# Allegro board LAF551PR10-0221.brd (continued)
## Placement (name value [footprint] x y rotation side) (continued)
CG268  22U_0603_6.3V6M  [C_0603]  263.22 57.01 270 bottom
CG269  10U_0603_6.3V6M  [C_0603]  271.41 114.67 180 top
CG270  10U_0603_6.3V6M  [C_0603]  234.9 89.84 90 top
CG271  10U_0603_6.3V6M  [C_0603]  247.21 52.06 0 bottom
CG272  1U_0402_6.3V4Z  [C_0402]  235.53 81.13 90 top
CG273  1U_0402_6.3V4Z  [C_0402]  245.17 52.12 0 bottom
CG274  1U_0402_6.3V4Z  [C_0402]  192.97 70.16 0 bottom
CG275  1U_0402_6.3V4Z  [C_0402]  223.29 79.49 180 top
CG276  1U_0402_6.3V4Z  [C_0402]  190.57 79 270 bottom
CG277  1U_0402_6.3V4Z  [C_0402]  193.32 85.14 180 bottom
CG278  22U_0603_6.3V6M  [C_0603]  231.78 56.19 270 bottom
CG279  22U_0603_6.3V6M  [C_0603]  263.22 67.3 90 bottom
CG280  22U_0603_6.3V6M  [C_0603]  263.22 66.28 270 bottom
CG281  10U_0603_6.3V6M  [C_0603]  285.19 80.19 270 bottom
CG282  10U_0603_6.3V6M  [C_0603]  254.33 52 180 bottom
CG283  10U_0603_6.3V6M  [C_0603]  204.22 88.07 0 bottom
CG284  1U_0402_6.3V4Z  [C_0402]  193.67 104.19 0 bottom
CG285  1U_0402_6.3V4Z  [C_0402]  196.36 70.16 180 bottom
CG286  1U_0402_6.3V4Z  [C_0402]  224.24 52.12 180 bottom
CG287  1U_0402_6.3V4Z  [C_0402]  196.36 104.19 180 bottom
CG288  22U_0603_6.3V6M  [C_0603]  194.19 114.86 180 bottom
CG289  10U_0603_6.3V6M  [C_0603]  192.62 111.34 270 bottom
CG290  10U_0603_6.3V6M  [C_0603]  230.26 118.48 90 top
CG291  4.7U_0402_6.3V6M  [C_0402]  227.21 110.62 270 top
CG292  1U_0402_6.3V4Z  [C_0402]  192.78 112.93 90 bottom
CG293  0.1U_0201_6.3V6K  [C_0201]  194.18 110.57 270 bottom
CG294  0.1U_0201_6.3V6K  [C_0201]  192.3 112.25 180 bottom
CG295  4.7U_0402_6.3V6M  [C_0402]  220.54 103.99 90 top
CG296  4.7U_0402_6.3V6M  [C_0402]  218.06 107.43 0 top
CG297  4.7U_0402_6.3V6M  [C_0402]  236.8 110.37 270 top
CG298  1U_0402_6.3V4Z  [C_0402]  219.59 103.99 90 top
CG299  1U_0402_6.3V4Z  [C_0402]  221.32 108.7 180 top
CG300  1U_0402_6.3V4Z  [C_0402]  237.88 110.37 270 top
CG301  0.1U_0201_6.3V6K  [C_0201]  239.02 112.35 90 top
CG302  0.1U_0201_6.3V6K  [C_0201]  220.48 106.51 90 top
CG303  0.1U_0201_6.3V6K  [C_0201]  221.59 110.16 0 top
CG304  0.1U_0201_6.3V6K  [C_0201]  239.72 110.2 270 top
CG305  0.1U_0201_6.3V6K  [C_0201]  223.24 106.61 0 top
CG306  0.1U_0201_6.3V6K  [C_0201]  219.85 106.51 90 top
CG307  0.1U_0201_6.3V6K  [C_0201]  220.48 110.95 90 top
CG308  0.1U_0402_10V7K  [C_0402]  241.87 115.05 90 top
CG309  0.1U_0402_10V7K  [C_0402]  242.96 115.19 0 top
CG310  1U_0402_6.3V6K  [C_0402]  230.3 109.73 180 top
CG311  4.7U_0603_6.3V6M  [C_0603]  245.14 113.76 90 top
CG312  0.1U_0402_10V7K  [C_0402]  218.7 104 90 top
CG313  0.01U_0402_16V7K  [C_0402]  276.32 103.2 270 top
CG314  0.01U_0402_16V7K  [C_0402]  272.74 104.36 90 top
CG315  0.01U_0402_16V7K  [C_0402]  264.85 62.11 270 bottom
CG316  0.01U_0402_16V7K  [C_0402]  274.6 68.47 180 top
CG317  0.01U_0402_16V7K  [C_0402]  229.4 64.75 180 top
CG318  0.01U_0402_16V7K  [C_0402]  230.93 62.09 0 top
CG320  10U_0402_6.3V6M  [C_0402]  195.03 110.87 270 bottom
CG322  1U_0402_6.3V6K  [C_0402]  196.58 105.83 90 bottom
CG323  0.1U_0402_16V7K  [C_0402]  196.57 108.55 270 bottom
CG324  22U_0402_6.3V6M  [C_0402]  277.73 115.64 270 top
CG325  10U_0402_6.3V4Z  [C_0402]  271.36 111.5 180 top
CG326  10U_0402_6.3V4Z  [C_0402]  270.95 106.06 180 top
CG327  10U_0402_6.3V4Z  [C_0402]  279.32 112.25 180 top
CG328  1U_0402_6.3V4Z  [C_0402]  270.52 119.51 0 top
CG329  1U_0402_6.3V4Z  [C_0402]  273.8 114.8 0 top
CG330  1U_0402_6.3V4Z  [C_0402]  281.1 112.28 180 top
CG331  1U_0402_6.3V4Z  [C_0402]  273.8 113.86 0 top
CG332  1U_0402_6.3V4Z  [C_0402]  271.36 112.44 180 top
CG333  1U_0402_6.3V4Z  [C_0402]  278.33 106.12 0 top
CG334  1U_0402_6.3V4Z  [C_0402]  281.64 101.96 180 top
CG335  1U_0402_6.3V4Z  [C_0402]  273.03 95.77 0 top
CG336  1U_0402_6.3V4Z  [C_0402]  278.46 101.73 180 top
CG337  1U_0402_6.3V4Z  [C_0402]  272.27 87.79 0 top
CG338  1U_0402_6.3V4Z  [C_0402]  278.46 100.84 180 top
CG339  1U_0402_6.3V4Z  [C_0402]  278.98 94.92 180 top
CG340  1U_0402_6.3V4Z  [C_0402]  271.28 95.79 0 top
CG341  1U_0402_6.3V4Z  [C_0402]  269.54 95.79 0 top
CG342  1U_0402_6.3V4Z  [C_0402]  272.23 100.55 180 top
CG343  1U_0402_6.3V4Z  [C_0402]  270.46 100.54 180 top
CG344  22U_0402_6.3V6M  [C_0402]  262.48 55.5 270 top
CG345  10U_0402_6.3V4Z  [C_0402]  248.71 58.87 270 top
CG346  10U_0402_6.3V4Z  [C_0402]  248.69 56.2 90 top
CG347  10U_0402_6.3V4Z  [C_0402]  256.55 55.54 270 top
CG348  1U_0402_6.3V4Z  [C_0402]  259.67 52.38 180 top
CG349  1U_0402_6.3V4Z  [C_0402]  254.64 55.45 270 top
CG350  1U_0402_6.3V4Z  [C_0402]  256.37 57.56 270 top
CG351  1U_0402_6.3V4Z  [C_0402]  254.63 58.12 90 top
CG352  1U_0402_6.3V4Z  [C_0402]  257.31 66.09 270 top
CG353  1U_0402_6.3V4Z  [C_0402]  253.88 63.49 270 top
CG354  1U_0402_6.3V4Z  [C_0402]  272.12 84.51 0 top
CG355  1U_0402_6.3V4Z  [C_0402]  270.66 84.52 180 top
CG356  1U_0402_6.3V4Z  [C_0402]  269.57 79.87 0 top
CG357  1U_0402_6.3V4Z  [C_0402]  271.4 79.9 0 top
CG358  1U_0402_6.3V4Z  [C_0402]  280.93 71.3 0 top
CG359  1U_0402_6.3V4Z  [C_0402]  271.48 77.46 180 top
CG360  1U_0402_6.3V4Z  [C_0402]  277.61 75.02 270 top
CG361  1U_0402_6.3V4Z  [C_0402]  272.56 71.72 180 top
CG362  1U_0402_6.3V4Z  [C_0402]  275.17 74.92 90 top
CG363  1U_0402_6.3V4Z  [C_0402]  273.22 76.57 180 top
CG364  22U_0402_6.3V6M  [C_0402]  219.07 52.34 180 top
CG365  10U_0402_6.3V4Z  [C_0402]  219.81 63.41 270 top
CG366  10U_0402_6.3V4Z  [C_0402]  215.64 52.26 0 top
CG367  10U_0402_6.3V4Z  [C_0402]  221.38 64.35 270 top
CG368  1U_0402_6.3V4Z  [C_0402]  229.28 66.56 270 bottom
CG369  1U_0402_6.3V4Z  [C_0402]  220.09 57.67 90 top
CG370  1U_0402_6.3V4Z  [C_0402]  215.64 53.17 0 top
CG371  1U_0402_6.3V4Z  [C_0402]  213.79 52.29 0 top
CG372  1U_0402_6.3V4Z  [C_0402]  213.79 53.2 0 top
CG373  1U_0402_6.3V4Z  [C_0402]  223.68 59.64 0 top
CG374  1U_0402_6.3V4Z  [C_0402]  231.82 60.3 90 top
CG375  1U_0402_6.3V4Z  [C_0402]  232.23 66.37 90 top
CG376  1U_0402_6.3V4Z  [C_0402]  232.43 59.05 270 top
CG377  1U_0402_6.3V4Z  [C_0402]  235.1 52.4 180 top
CG378  1U_0402_6.3V4Z  [C_0402]  238.71 64.38 270 top
CG379  1U_0402_6.3V4Z  [C_0402]  238.64 55.57 270 top
CG380  1U_0402_6.3V4Z  [C_0402]  238.72 58.06 270 top
CG381  1U_0402_6.3V4Z  [C_0402]  236.51 59.67 180 top
CG382  1U_0402_6.3V4Z  [C_0402]  231.94 57.18 90 bottom
CG383  1U_0402_6.3V4Z  [C_0402]  232 63.81 270 bottom
CG384  0.1U_0402_10V7K  [C_0402]  194.37 106.1 0 top
CG385  10U_0402_6.3V6M  [C_0402]  197.46 108.55 270 bottom
CG386  0.1U_0402_10V7K  [C_0402]  196.74 116.31 0 bottom
CG387  0.01U_0402_16V7K  [C_0402]  199.25 87.85 90 bottom
CG388  0.01U_0402_16V7K  [C_0402]  200.12 86.29 270 bottom
CG389  22U_0402_6.3V6M  [C_0402]  191.26 100.8 270 top
CG390  10U_0402_6.3V4Z  [C_0402]  205.23 86.1 0 bottom
CG391  10U_0402_6.3V4Z  [C_0402]  194.64 88.7 180 bottom
CG392  10U_0402_6.3V4Z  [C_0402]  205.23 87 0 bottom
CG393  1U_0402_6.3V4Z  [C_0402]  200.87 104.19 180 top
CG394  1U_0402_6.3V4Z  [C_0402]  195.88 97.49 0 top
CG395  1U_0402_6.3V4Z  [C_0402]  202.92 103.22 180 top
CG396  1U_0402_6.3V4Z  [C_0402]  193.93 97.56 180 top
CG397  1U_0402_6.3V4Z  [C_0402]  202.61 95.8 0 top
CG398  1U_0402_6.3V4Z  [C_0402]  204.48 95.95 0 top
CG399  1U_0402_6.3V4Z  [C_0402]  194.65 69.75 180 top
CG400  1U_0402_6.3V4Z  [C_0402]  190.62 80.79 0 top
CG401  1U_0402_6.3V4Z  [C_0402]  204.9 70.42 0 top
CG402  1U_0402_6.3V4Z  [C_0402]  196.92 76.91 180 top
CG403  1U_0402_6.3V4Z  [C_0402]  197.95 80.57 90 top
CG404  1U_0402_6.3V4Z  [C_0402]  206.75 75.49 180 top
CG405  1U_0402_6.3V4Z  [C_0402]  191.36 75.29 270 top
CG406  1U_0402_6.3V4Z  [C_0402]  201.74 70.53 0 top
CG407  1U_0402_6.3V4Z  [C_0402]  204.02 70.44 90 top
CG408  1U_0402_6.3V4Z  [C_0402]  198.05 70.23 90 top
CG410  22U_0402_6.3V6M  [C_0402]  267.88 91.94 270 top
CG411  22U_0402_6.3V6M  [C_0402]  268.75 91.96 270 top
CG412  22U_0402_6.3V6M  [C_0402]  273.63 93.34 0 top
CG413  10U_0402_6.3V4Z  [C_0402]  278.51 97.46 180 top
CG414  10U_0402_6.3V4Z  [C_0402]  278.45 102.62 180 top
CG415  10U_0402_6.3V4Z  [C_0402]  279.82 94.91 0 top
CG416  1U_0402_6.3V4Z  [C_0402]  270.46 101.44 180 top
CG417  1U_0402_6.3V4Z  [C_0402]  268.63 96.54 90 top
CG418  1U_0402_6.3V4Z  [C_0402]  272.26 86.87 0 top
CG419  1U_0402_6.3V4Z  [C_0402]  271.78 93.75 180 top
CG420  1U_0402_6.3V4Z  [C_0402]  268.54 99.79 270 top
CG421  1U_0402_6.3V4Z  [C_0402]  276.7 96.59 0 top
CG422  1U_0402_6.3V4Z  [C_0402]  273.06 94.89 180 top
CG423  1U_0402_6.3V4Z  [C_0402]  275.64 91.84 90 top
CG424  1U_0402_6.3V4Z  [C_0402]  276.56 91.84 90 top
CG425  1U_0402_6.3V4Z  [C_0402]  269.55 94.81 0 top
CG426  22U_0402_6.3V6M  [C_0402]  259.69 51.49 180 top
CG427  22U_0402_6.3V6M  [C_0402]  263.36 55.52 270 top
CG428  22U_0402_6.3V6M  [C_0402]  255.51 58.12 90 top
CG429  10U_0402_6.3V4Z  [C_0402]  250.62 56.35 270 top
CG430  10U_0402_6.3V4Z  [C_0402]  254.05 52.47 180 top
CG431  10U_0402_6.3V4Z  [C_0402]  256.31 67.06 0 top
CG432  1U_0402_6.3V4Z  [C_0402]  254.69 65.83 90 top
CG433  1U_0402_6.3V4Z  [C_0402]  249.34 65.05 270 top
CG434  1U_0402_6.3V4Z  [C_0402]  263.34 57.31 270 top
CG435  1U_0402_6.3V4Z  [C_0402]  254.77 63.49 270 top
CG436  1U_0402_6.3V4Z  [C_0402]  257.21 52.43 180 top
CG437  1U_0402_6.3V4Z  [C_0402]  257.23 51.54 180 top
CG438  1U_0402_6.3V4Z  [C_0402]  258.83 62 180 top
CG439  1U_0402_6.3V4Z  [C_0402]  258.73 59.64 0 top
CG440  1U_0402_6.3V4Z  [C_0402]  254.06 51.58 180 top
CG441  1U_0402_6.3V4Z  [C_0402]  248.45 65.07 270 top
CG442  22U_0402_6.3V6M  [C_0402]  228.38 55.46 270 top
CG443  22U_0402_6.3V6M  [C_0402]  221.42 57.52 90 top
CG444  22U_0402_6.3V6M  [C_0402]  229.28 55.46 270 top
CG445  10U_0402_6.3V4Z  [C_0402]  227.48 57.25 270 top
CG446  10U_0402_6.3V4Z  [C_0402]  228.37 57.23 270 top
CG447  10U_0402_6.3V4Z  [C_0402]  227.5 55.46 270 top
CG448  1U_0402_6.3V4Z  [C_0402]  224.23 52.39 180 top
CG449  1U_0402_6.3V4Z  [C_0402]  222.3 59.31 180 top
CG450  1U_0402_6.3V4Z  [C_0402]  221.32 51.44 0 top
CG451  1U_0402_6.3V4Z  [C_0402]  221.32 52.34 0 top
CG452  1U_0402_6.3V4Z  [C_0402]  220.54 55.79 90 top
CG453  1U_0402_6.3V4Z  [C_0402]  220.35 53.7 180 top
CG454  1U_0402_6.3V4Z  [C_0402]  224.24 51.49 180 top
CG455  1U_0402_6.3V4Z  [C_0402]  221 65.83 90 top
CG456  1U_0402_6.3V4Z  [C_0402]  228.14 59.79 180 top
CG457  1U_0402_6.3V4Z  [C_0402]  221.42 55.78 90 top
CG458  22U_0402_6.3V6M  [C_0402]  201.7 95.86 270 top
CG459  22U_0402_6.3V6M  [C_0402]  197.18 103.81 270 top
CG460  22U_0402_6.3V6M  [C_0402]  192.02 103.58 0 top
CG461  10U_0402_6.3V4Z  [C_0402]  193.96 96.61 180 top
CG462  10U_0402_6.3V4Z  [C_0402]  204.26 97.25 0 top
CG463  10U_0402_6.3V4Z  [C_0402]  201.95 97.48 180 top
CG464  1U_0402_6.3V4Z  [C_0402]  200.14 98.42 270 top
CG465  1U_0402_6.3V4Z  [C_0402]  201.76 104.21 90 top
CG466  1U_0402_6.3V4Z  [C_0402]  202.8 104.11 90 top
CG467  1U_0402_6.3V4Z  [C_0402]  204.85 104.44 180 top
CG468  1U_0402_6.3V4Z  [C_0402]  190.33 92.9 270 top
CG469  1U_0402_6.3V4Z  [C_0402]  192.16 95.69 90 top
CG470  1U_0402_6.3V4Z  [C_0402]  191.3 98.11 90 top
CG471  1U_0402_6.3V4Z  [C_0402]  200.87 105.08 180 top
CG472  1U_0402_6.3V4Z  [C_0402]  198.61 94.44 0 top
CG473  1U_0402_6.3V4Z  [C_0402]  198.54 96.73 180 top
CG474  0.1U_0402_16V4Z  [C_0402]  197.89 113.25 0 top
CG475  0.1U_0402_16V4Z  [C_0402]  196.58 106.28 270 top
CG476  0.1U_0201_6.3V6K  [C_0201]  314.31 62.12 270 top
CG478  0.1U_0201_6.3V6K  [C_0201]  277.36 156.96 90 top
CG479  0.1U_0201_6.3V6K  [C_0201]  280.35 163.13 0 top
CG480  0.1U_0201_6.3V6K  [C_0201]  275.69 149.57 270 top
CG481  2200P_0402_25V7K  [C_0402]  281.64 164.34 180 top
CG482  0.047U_0402_16V4Z  [C_0402]  278.2 164.25 270 top
CG483  0.1U_0201_6.3V6K  [C_0201]  281.21 145.91 270 top
CG487  0.1U_0402_16V7K  [C_0402]  193.16 111.34 180 top
CG488  0.1U_0402_10V7K  [C_0402]  191.4 58.78 90 bottom
CG489  0.01U_0402_16V  [C_0402]  215.32 157.17 0 top
CH36  4.7U_0402_6.3V6M  [C_0402]  219.52 38.92 0 bottom
CH45  10P_0402_50V8J  [C_0402]  212.43 14.41 180 bottom
CH46  10P_0402_50V8J  [C_0402]  213.29 14.41 0 bottom
CH47  15P_0402_50V  [C_0402]  192.69 45.32 180 bottom
CH48  15P_0402_50V  [C_0402]  195.23 45.32 0 bottom
CH49  0.1U_0402_16V7K  [C_0402]  229.09 16.08 0 bottom
CH52  1U_0603_10V6K~D  [C_0603]  228.65 14.38 0 bottom
CH53  1U_0603_10V6K~D  [C_0603]  216.89 14.23 180 bottom
CH80  1U_0402_6.3V6K~D  [C_0402]  213.66 15.99 180 top
CH82  1U_0402_6.3V6K~D  [C_0402]  190.56 41.99 180 bottom
CH100  0.022U_0402_25V7K  [C_0402]  152.66 39.38 0 top
CH101  0.022U_0402_25V7K  [C_0402]  155.34 55.37 90 top
CH102  10U_0603_6.3V6M~D  [C_0603]  168.05 106.97 270 top
CH103  10U_0603_6.3V6M~D  [C_0603]  168.05 109.38 270 top
CH104  10U_0603_6.3V6M~D  [C_0603]  167.94 111.78 90 top
CH105  1U_0201_6.3V6M  [C_0201]  172.5 116.34 0 top
CH106  1U_0201_6.3V6M  [C_0201]  169.43 116.73 90 top
CH107  1U_0201_6.3V6M  [C_0201]  167.98 115.01 0 top
CH118  10U_0402_6.3V6M  [C_0402]  144.22 101.39 90 top
CH119  10U_0402_6.3V6M  [C_0402]  150.82 101.83 90 top
CH120  10U_0402_6.3V6M  [C_0402]  171.46 100.89 0 top
CH121  10U_0402_6.3V6M  [C_0402]  147.76 81.31 0 top
CH122  10U_0402_6.3V6M  [C_0402]  152.49 101.64 90 top
CH123  10U_0402_6.3V6M  [C_0402]  147.76 80.04 0 top
CH124  10U_0402_6.3V6M  [C_0402]  143.26 98.78 90 top
CH125  10U_0402_6.3V6M  [C_0402]  156.18 101.46 90 top
CH126  10U_0402_6.3V6M  [C_0402]  167.9 97.88 90 top
CH127  10U_0402_6.3V6M  [C_0402]  165.3 99.34 90 top
CH128  10U_0402_6.3V6M  [C_0402]  147.76 78.77 0 top
CH129  22U_0603_6.3V6M  [C_0603]  168.15 81.05 0 top
CH130  22U_0603_6.3V6M  [C_0603]  168.15 79.34 0 top
CH131  22U_0603_6.3V6M  [C_0603]  153.57 79.14 180 top
CH132  22U_0603_6.3V6M  [C_0603]  153.57 80.98 180 top
CH173  0.1U_0402_10V7K  [C_0402]  213.66 15.1 180 top
CH174  0.1U_0402_10V  [C_0402]  215.96 20.69 0 top
CH175  0.1U_0402_10V  [C_0402]  212.91 44.85 90 bottom
CH176  1U_0402_6.3V6K~D  [C_0402]  213.93 35.49 0 top
CH180  1U_0402_6.3V6K~D  [C_0402]  204.4 26.04 180 top
CH181  22U_0805_6.3V6M~D  [C_0805]  202.89 15.26 270 bottom
CH182  1U_0603_10V6K  [C_0603]  214.25 38.18 0 top
CH186  0.1U_0402_10V7K  [C_0402]  216.09 17.1 180 top
CH187  1U_0402_6.3V6K~D  [C_0402]  194.73 17.07 180 top
CH188  1U_0402_6.3V6K~D  [C_0402]  206.94 26.34 90 top
CH190  0.1U_0402_10V7K  [C_0402]  202.94 21.83 0 top
CH192  0.1U_0402_10V7K  [C_0402]  206.05 25.17 90 top
CH193  0.1U_0402_16V7K~D  [C_0402]  172.79 102.28 90 top
CH194  0.1U_0402_16V7K~D  [C_0402]  130.9 116.77 180 top
CH195  0.1U_0402_16V7K~D  [C_0402]  132.33 117.28 0 top
CH197  0.1U_0402_10V7K  [C_0402]  125.57 77.69 270 top
CH201  0.1U_0201_6.3V6K  [C_0201]  220.99 38.57 270 top
CH202  0.22U_0201_6.3V  [C_0201]  250.58 12.22 270 top
CH203  0.22U_0201_6.3V  [C_0201]  250.01 12.22 270 top
CH204  0.22U_0201_6.3V  [C_0201]  189.26 26.09 0 bottom
CH205  0.22U_0201_6.3V  [C_0201]  189.26 26.66 0 bottom
CH206  0.22U_0201_6.3V  [C_0201]  191.63 23.99 180 bottom
CH207  0.22U_0201_6.3V  [C_0201]  191.63 24.57 180 bottom
CH208  0.22U_0201_6.3V  [C_0201]  241.05 11.7 90 top
CH209  0.22U_0201_6.3V  [C_0201]  241.63 11.7 90 top
CH210  0.22U_0201_6.3V  [C_0201]  189.96 19.99 0 bottom
CH211  0.22U_0201_6.3V  [C_0201]  189.96 19.42 0 bottom
CH212  0.22U_0201_6.3V  [C_0201]  188.88 21.2 0 bottom
CH213  0.22U_0201_6.3V  [C_0201]  188.88 21.77 0 bottom
CH214  0.22U_0201_6.3V  [C_0201]  190.67 18.28 180 bottom
CH215  0.22U_0201_6.3V  [C_0201]  190.67 18.85 180 bottom
CH216  0.22U_0201_6.3V  [C_0201]  190.55 17.64 180 bottom
CH217  0.22U_0201_6.3V  [C_0201]  190.55 16.88 180 bottom
CH218  0.22U_0201_6.3V  [C_0201]  267.95 16.93 90 bottom
CH219  0.22U_0201_6.3V  [C_0201]  267.32 16.93 90 bottom
CH220  0.22U_0201_6.3V  [C_0201]  269.67 17.52 180 bottom
CH221  0.22U_0201_6.3V  [C_0201]  269.67 16.95 180 bottom
CH222  0.22U_0201_6.3V  [C_0201]  197.62 14.88 90 bottom
CH223  0.22U_0201_6.3V  [C_0201]  197.05 14.88 90 bottom
CH224  0.22U_0201_6.3V  [C_0201]  198.19 14.88 90 bottom
CH225  0.22U_0201_6.3V  [C_0201]  198.76 14.88 90 bottom
CH226  0.1U_0402_10V7K  [C_0402]  216.82 14.51 0 top
CH227  0.01U_0201_16V7  [C_0201]  188.29 24.48 270 bottom
CH228  0.01U_0201_16V7  [C_0201]  187.59 24.48 270 bottom
CH229  0.01U_0201_16V7  [C_0201]  104.66 13.03 90 bottom
CH230  0.01U_0201_16V7  [C_0201]  105.23 13.03 90 bottom
CH231  10P_0402_50V8J  [C_0402]  206.94 24.59 90 top
CH232  33P_0402_50V8J  [C_0402]  222.49 21.11 90 bottom
CH233  4.7U_0603_6.3V6M  [C_0603]  212.35 35.11 270 top
CI38  0.1U_0402_10V6K  [C_0402]  165.68 175.57 90 bottom
CI39  0.1U_0402_10V6K  [C_0402]  166.57 175.57 90 bottom
CL1  0.1U_0402_16V7K  [C_0402]  268.56 165.47 180 bottom
CL2  0.1U_0402_16V7K  [C_0402]  268.56 164.58 180 bottom
CL3  0.1U_0402_16V7K  [C_0402]  271.8 167.68 90 bottom
CL4  0.1U_0402_16V7K  [C_0402]  272.69 167.68 90 bottom
CL5  1U_0402_6.3V6K~D  [C_0402]  275.35 162.26 180 top
CL6  0.1U_0402_16V7K~D  [C_0402]  275.34 161.37 180 top
CL7  0.1U_0402_16V7K~D  [C_0402]  267.38 161.46 180 bottom
CL8  18P_0201_25V  [C_0201]  280.32 165.22 0 bottom
CL9  18P_0201_25V  [C_0201]  279.7 165.22 180 bottom
CL11  1000P_0402_50V7K~D  [C_0402]  276.63 166.93 0 bottom
CL12  0.1U_0402_16V7K~D  [C_0402]  269.59 168.82 180 top
CL13  1U_0402_6.3V6K~D  [C_0402]  269.59 167.94 180 top
CL14  10U_0603_6.3V6M~D  [C_0603]  269.77 169.9 180 top
CL15  10U_0603_6.3V6M~D  [C_0603]  269.77 171.17 180 top
CL16  0.1U_0402_16V7K~D  [C_0402]  272.54 159.59 90 top
CL17  1U_0402_6.3V6K~D  [C_0402]  274.3 159.59 90 top
CL18  1U_0402_6.3V6K~D  [C_0402]  275.35 163.15 180 top
CL19  0.1U_0402_16V7K~D  [C_0402]  275.34 164.04 180 top
CL20  0.1U_0402_16V7K~D  [C_0402]  271.6 166.4 270 top
CL21  1U_0402_6.3V6K~D  [C_0402]  270.71 166.4 270 top
CL22  4.7U_0603_6.3V6K~D  [C_0603]  272.51 167.31 90 top
CL23  0.1U_0402_16V7K~D  [C_0402]  269.82 166.4 270 top
CL24  0.1U_0402_16V7K~D  [C_0402]  273.43 159.59 90 top
CL25  0.1U_0402_16V7K~D  [C_0402]  271.65 159.59 90 top
CL27  470P_0402_50V7K  [C_0402]  242.71 171.83 270 top
CL28  470P_0402_50V7K  [C_0402]  263.47 160.21 270 top
CL29  470P_0402_50V7K  [C_0402]  264.36 160.21 270 top
CL30  10P_1808_3KV7K~D  [C_1808]  263.03 160.46 90 bottom
CL31  470P_0402_50V7K  [C_0402]  266.12 161.6 0 top
CL32  1000P_0402_50V7K~D  [C_0402]  250.83 158.56 270 top
CL33  0.1U_0402_16V7K~D  [C_0402]  247.91 157.65 90 top
CL34  1000P_0402_50V7K~D  [C_0402]  247.02 158.56 270 top
CL35  0.1U_0402_16V7K~D  [C_0402]  249.94 157.65 90 top
CL36  1000P_0402_50V7K~D  [C_0402]  254.96 158.56 270 top
CL37  0.1U_0402_16V7K~D  [C_0402]  255.85 157.65 90 top
CL38  1000P_0402_50V7K~D  [C_0402]  257.44 158.56 270 top
CL39  0.1U_0402_16V7K~D  [C_0402]  258.33 157.65 90 top
CL40  4.7U_0805_10V4Z  [C_0805]  269.97 173.47 180 bottom
CL41  0.1U_0402_16V7K  [C_0402]  271.03 173.02 90 bottom
CL42  0.1U_0402_16V7K  [C_0402]  266.96 172.09 270 bottom
CL43  1U_0402_6.3V6K~D  [C_0402]  273.38 166.4 270 top
CL44  0.1U_0402_16V7K~D  [C_0402]  272.49 166.4 270 top
CLRP1  SHORT PADS  [SHORTPADS]  173.94 35.87 90 bottom
CM9  0.1U_0402_10V7K  [C_0402]  134.11 162.19 90 bottom
CM10  0.1U_0402_10V7K  [C_0402]  302.88 43.79 90 top
CM11  4.7U_0805_10V4Z  [C_0805]  314.23 43.87 180 top
CM12  22U_0603_6.3V6M~D  [C_0603]  301.8 42.59 90 top
CM13  0.1U_0402_10V7K~D  [C_0402]  300.72 42.58 90 top
CM14  22U_0603_6.3V6M~D  [C_0603]  315.54 43.17 90 top
CM15  0.1U_0402_10V7K~D  [C_0402]  315.73 41.98 270 top
CM16  0.1U_0402_10V7K  [C_0402]  172.4 161.22 0 bottom
CM17  0.1U_0402_10V7K  [C_0402]  172.4 162.11 0 bottom
CM18  0.1U_0402_10V7K  [C_0402]  168.41 163.17 90 bottom
CM19  22U_0603_6.3V6M  [C_0603]  165.91 154.13 180 bottom
CM20  0.1U_0402_10V7K  [C_0402]  168.34 154.16 270 bottom
CM21  1U_0402_6.3V  [C_0402]  165.11 162.82 90 top
CM23  0.1U_0402_10V7K  [C_0402]  162.25 176.29 270 bottom
CM29  10U_0603_6.3V6M  [C_0603]  125.98 153.19 0 top
CM30  1U_0402_6.3V  [C_0402]  125.23 157 180 bottom
CM31  10U_0603_6.3V6M  [C_0603]  125.98 154.97 0 top
CM32  0.1U_0402_10V7K  [C_0402]  131.12 153.27 270 bottom
CM33  1U_0402_6.3V  [C_0402]  125.23 157.89 180 bottom
CM34  0.1U_0402_10V7K  [C_0402]  138.43 157.34 0 bottom
CM35  0.1U_0402_10V7K  [C_0402]  129.6 153.27 270 bottom
CM36  0.1U_0402_10V7K  [C_0402]  130.74 162.19 90 bottom
CM62  0.22U_0201_6.3V  [C_0201]  133.22 150.45 90 bottom
CM63  0.22U_0201_6.3V  [C_0201]  132.97 152.35 90 bottom
CM64  0.22U_0201_6.3V  [C_0201]  136.9 150.45 90 bottom
CM65  0.22U_0201_6.3V  [C_0201]  136.01 150.45 90 bottom
CM66  0.22U_0201_6.3V  [C_0201]  132.08 152.35 90 bottom
CM67  0.22U_0201_6.3V  [C_0201]  135.57 152.35 90 bottom
CM68  0.22U_0201_6.3V  [C_0201]  134.11 150.45 90 bottom
CM69  0.22U_0201_6.3V  [C_0201]  134.68 152.35 90 bottom
CM70  0.1U_0402_10V7K  [C_0402]  149.61 172.72 270 bottom
CM98  0.01U_0402_16V7K  [C_0402]  163.36 164.61 180 bottom
CM99  0.01U_0402_16V7K  [C_0402]  163.36 163.48 180 bottom
CM100  10P_0402_50V8J  [C_0402]  318.58 42.95 90 top
CN9  1U_0402_10V6K  [C_0402]  312.81 41.08 90 top
CN23  0.1U_0402_16V7K  [C_0402]  314.32 39.49 180 top
CN24  0.1U_0402_16V7K  [C_0402]  314.32 38.46 180 top
CN25  1U_0402_10V6K  [C_0402]  316.67 38.76 0 top
CS1  10U_0603_25V6M  [C_0603]  127.45 11.93 270 top
CS2  10U_0603_6.3V6M  [C_0603]  183.99 64.25 180 top
CS5  1000P_0402_50V7K~D  [C_0402]  125.48 11.94 270 top
CS6  0.1U_0402_25V6K~D  [C_0402]  126.37 11.94 270 top
CS7  0.1U_0402_16V4Z  [C_0402]  182.58 68 180 top
CS16  22U_0402_6.3V6M  [C_0402]  125.68 13.25 90 top
CT1  0.22U_0201_6.3V  [C_0201]  188.35 164.41 180 top
CT2  0.22U_0201_6.3V  [C_0201]  188.35 164.98 180 top
CT3  0.22U_0201_6.3V  [C_0201]  188.35 162.12 180 top
CT4  0.22U_0201_6.3V  [C_0201]  188.35 166.12 180 top
CT5  0.22U_0201_6.3V  [C_0201]  188.35 168.41 180 top
CT6  0.1U_0201_6.3V6K  [C_0201]  177.42 159.23 90 top
CT7  0.1U_0201_6.3V6K  [C_0201]  177.99 159.23 90 top
CT8  0.1U_0201_6.3V6K  [C_0201]  179.14 159.23 90 top
CT9  0.1U_0201_6.3V6K  [C_0201]  178.57 159.23 90 top
CT10  0.1U_0201_6.3V6K  [C_0201]  180.28 159.23 90 top
CT11  0.1U_0201_6.3V6K  [C_0201]  181.42 159.23 90 top
CT12  0.22U_0201_6.3V  [C_0201]  188.35 165.55 180 top
CT13  0.22U_0201_6.3V  [C_0201]  188.35 163.84 180 top
CT14  0.22U_0201_6.3V  [C_0201]  190.71 162.71 180 top
CT15  0.22U_0201_6.3V  [C_0201]  188.35 161.55 180 top
CT16  0.22U_0201_6.3V  [C_0201]  190.71 162.14 180 top
CT18  0.22U_0201_6.3V  [C_0201]  188.35 166.7 180 top
CT21  0.22U_0201_6.3V  [C_0201]  188.35 168.98 180 top
CT23  0.1U_0201_6.3V6K  [C_0201]  179.71 159.23 90 top
CT24  0.1U_0201_6.3V6K  [C_0201]  180.85 159.23 90 top
CT25  0.1U_0201_6.3V6K  [C_0201]  179.39 154.49 90 bottom
CT26  0.1U_0201_6.3V6K  [C_0201]  178.82 154.49 90 bottom
CT27  0.1U_0201_6.3V6K  [C_0201]  182.57 159.23 90 top
CT28  0.1U_0201_6.3V6K  [C_0201]  182 159.23 90 top
CT29  0.1U_0201_6.3V6K  [C_0201]  183.71 159.23 90 top
CT30  0.1U_0201_6.3V6K  [C_0201]  183.14 159.23 90 top
CT31  0.1U_0201_6.3V6K  [C_0201]  184.85 159.23 90 top
CT32  0.1U_0201_6.3V6K  [C_0201]  184.28 159.23 90 top
CT33  0.1U_0201_6.3V6K  [C_0201]  186 159.23 90 top
CT34  0.1U_0201_6.3V6K  [C_0201]  185.42 159.23 90 top
CT35  0.1U_0201_6.3V6K  [C_0201]  181.35 154.49 90 bottom
CT36  0.1U_0201_6.3V6K  [C_0201]  181.95 154.48 90 bottom
CT37  27P_0201_25V  [C_0201]  189.44 167.55 90 bottom
CT38  27P_0201_25V  [C_0201]  189.44 166.92 270 bottom
CT39  0.22U_0201_6.3V  [C_0201]  183.15 174.48 270 top
CT40  0.22U_0201_6.3V  [C_0201]  182.58 174.48 270 top
CT41  0.22U_0201_6.3V  [C_0201]  184.04 174.48 270 top
CT42  0.22U_0201_6.3V  [C_0201]  184.61 174.48 270 top
CT43  0.1U_0201_6.3V6K  [C_0201]  182.62 161.47 90 bottom
CT44  0.1U_0201_6.3V6K  [C_0201]  182.05 161.47 90 bottom
CT45  0.1U_0201_6.3V6K  [C_0201]  188.9 153.9 180 bottom
CT46  0.1U_0201_6.3V6K  [C_0201]  178.75 164.34 270 bottom
CT47  1U_0201_6.3V6M  [C_0201]  178.11 169.48 270 bottom
CT48  1U_0201_6.3V6M  [C_0201]  176.17 172.8 180 bottom
CT49  1U_0201_6.3V6M  [C_0201]  176.43 173.92 180 top
CT50  10U_0402_6.3V6M  [C_0402]  176.87 174.68 180 top
CT51  10U_0402_6.3V6M  [C_0402]  176.87 175.57 180 top
CT52  10U_0402_6.3V6M  [C_0402]  176.87 176.46 180 top
CT53  10U_0402_6.3V6M  [C_0402]  177.73 176.46 0 top
CT54  1U_0201_6.3V6M  [C_0201]  180.03 166.84 270 bottom
CT55  1U_0201_6.3V6M  [C_0201]  184.57 165.6 0 bottom
CT56  1U_0201_6.3V6M  [C_0201]  187.18 159.85 180 top
CT57  1U_0201_6.3V6M  [C_0201]  175.45 154.82 270 bottom
CT58  1U_0201_6.3V6M  [C_0201]  174.81 154.82 270 bottom
CT59  1U_0201_6.3V6M  [C_0201]  181.29 167.01 270 bottom
CT60  1U_0201_6.3V6M  [C_0201]  181.86 164.33 270 bottom
CT61  1U_0201_6.3V6M  [C_0201]  179.38 166.82 270 bottom
CT62  1U_0201_6.3V6M  [C_0201]  178.6 167.48 180 bottom
CT63  1U_0201_6.3V6M  [C_0201]  179.4 170.4 270 bottom
CT64  1U_0201_6.3V6M  [C_0201]  180.41 171.02 90 bottom
CT65  1U_0201_6.3V6M  [C_0201]  179.84 171.02 90 bottom
CT66  1U_0201_6.3V6M  [C_0201]  180.98 171.02 90 bottom
CT67  1U_0201_6.3V6M  [C_0201]  179.24 171.61 180 bottom
CT68  1U_0201_6.3V6M  [C_0201]  179.24 171.03 180 bottom
CT69  1U_0201_6.3V6M  [C_0201]  181.56 171.02 90 bottom
CT70  1U_0201_6.3V6M  [C_0201]  187.8 159.79 0 top
CT71  1U_0201_6.3V6M  [C_0201]  183.93 166.23 0 bottom
CT72  1U_0201_6.3V6M  [C_0201]  183.12 166.23 180 bottom
CT73  47U_0603_6.3V6M  [C_0603]  173.44 175.02 90 bottom
CT74  47U_0603_6.3V6M  [C_0603]  172.22 175.02 90 bottom
CT75  47U_0603_6.3V6M  [C_0603]  171 175.02 90 bottom
CT77  1U_0201_6.3V6M  [C_0201]  183.17 164.37 0 bottom
CT78  1U_0201_6.3V6M  [C_0201]  179.38 164.34 270 bottom
CT79  1U_0201_6.3V6M  [C_0201]  181.29 165.22 90 bottom
CT80  1U_0201_6.3V6M  [C_0201]  180.03 165.05 90 bottom
CT81  10U_0402_6.3V6M  [C_0402]  183.54 170.6 90 bottom
CT82  10U_0402_6.3V6M  [C_0402]  182.65 170.6 90 bottom
CT83  1U_0201_6.3V6M  [C_0201]  181.15 168.96 180 bottom
CT84  1U_0201_6.3V6M  [C_0201]  183.42 168.77 0 bottom
CT85  1U_0201_6.3V6M  [C_0201]  183.97 168.05 270 bottom
CT86  1U_0201_6.3V6M  [C_0201]  182.63 168.13 90 bottom
CT88  0.1U_0402_10V6K  [C_0402]  195.6 166.36 180 top
CT90  22U_0603_6.3V6M  [C_0603]  203.83 160.11 180 bottom
CT91  22U_0603_6.3V6M  [C_0603]  203.83 158.85 180 bottom
CT92  22U_0603_6.3V6M  [C_0603]  204.72 161.95 0 bottom
CT93  22U_0603_6.3V6M  [C_0603]  204.72 163.16 0 bottom
CT94  0.47U_0402_25V6K  [C_0402]  194.9 181.35 180 top
CT95  0.47U_0402_25V6K  [C_0402]  190.31 179.75 0 top
CT96  0.47U_0402_25V6K  [C_0402]  193.18 179.42 0 top
CT97  0.47U_0402_25V6K  [C_0402]  191.28 181.39 180 top
CT98  2.2U_0603_16V6K  [C_0603]  195.75 163.02 180 bottom
CT99  4.7U_0603_10V6K  [C_0603]  196.8 160.35 180 bottom
CT100  4.7U_0603_10V6K  [C_0603]  198.26 166.93 90 top
CT101  1U_0402_6.3V6K  [C_0402]  197.1 165.98 0 top
CT102  1U_0201_6.3V6M  [C_0201]  196.24 169.32 90 top
CT103  10U_0402_6.3V6M  [C_0402]  196.12 165 270 bottom
CT104  0.22U_0402_10V4Z  [C_0402]  202.63 168.99 90 bottom
CT106  1U_0603_25V6K  [C_0603]  204.61 162.74 180 top
CT108  0.22U_0201_6.3V  [C_0201]  188.35 167.84 180 top
CT109  0.22U_0201_6.3V  [C_0201]  188.35 167.27 180 top
CT110  0.22U_0201_6.3V  [C_0201]  188.35 169.55 180 top
CT111  0.22U_0201_6.3V  [C_0201]  188.35 170.12 180 top
CT112  220P_0201_25V7K  [C_0201]  202.95 167.58 270 top
CT113  220P_0201_25V7K  [C_0201]  203.75 168.21 270 top
CT114  100P_0402_50V8J~D  [C_0402]  185.23 9.96 0 top
CT115  0.047U_0402_25V7K  [C_0402]  186.78 7.85 90 top
CT116  10U_0603_6.3V6M~D  [C_0603]  188.16 13.34 180 bottom
CT117  2200P_0402_25V7K  [C_0402]  192.24 9.52 180 top
CT118  0.1U_0402_10V6K  [C_0402]  193.86 7.8 0 top
CT153  1U_0201_6.3V6M  [C_0201]  181.9 165.54 0 bottom
CT154  47U_0603_6.3V6M  [C_0603]  175.94 168.05 180 bottom
CT155  47U_0603_6.3V6M  [C_0603]  175.94 169.24 180 bottom
CT156  22P_0402_50V8J~D  [C_0402]  195.36 158.68 0 bottom
CT157  22P_0402_50V8J~D  [C_0402]  197.25 159.01 45 bottom
CU2  47U_0805_6.3V6M  [C_0805]  20.11 45.43 0 bottom
CU3  10U_0603_6.3V6M~D  [C_0603]  20.58 40.76 0 bottom
CU6  150U_B2_6.3VM_R35M  [C_B2]  20.31 42.98 180 bottom
CU7  0.1U_0402_16V7K  [C_0402]  20.21 42.22 180 top
CU10  47U_0805_6.3V6M  [C_0805]  321.88 22.39 90 top
CU11  10U_0603_6.3V6M~D  [C_0603]  319.97 21.97 180 top
CU12  0.1U_0402_10V7K  [C_0402]  24.16 41.49 0 top
CU13  0.1U_0402_10V7K  [C_0402]  24.16 40.6 0 top
CU16  0.1U_0402_16V7K  [C_0402]  318.46 26.67 180 top
CU17  0.1U_0402_16V7K  [C_0402]  319.39 26.67 0 top
CU18  0.47U_0402_25V6K  [C_0402]  11.06 64.95 90 bottom
CU19  0.47U_0402_25V6K  [C_0402]  12.32 59.11 0 bottom
CU20  0.47U_0402_25V6K  [C_0402]  11.06 64.06 270 bottom
CU21  0.47U_0402_25V6K  [C_0402]  10.3 59.19 270 bottom
CU26  0.1U_0402_16V7K  [C_0402]  18.3 35.41 90 top
CU27  2.2U_0603_6.3V6K  [C_0603]  22.93 36.31 90 top
CU28  0.1U_0402_16V7K  [C_0402]  31.12 45.41 270 top
CU29  0.1U_0402_16V7K  [C_0402]  20.95 37.96 0 top
CU32  2.2U_0603_25V6K  [C_0603]  12.52 58.03 0 bottom
CU33  47U_0603_6.3V6M  [C_0603]  29.92 46.54 270 bottom
CU34  0.1U_0402_16V7K  [C_0402]  28.85 47.87 180 top
CU35  0.1U_0402_16V7K  [C_0402]  28.28 46.09 180 top
CU37  10U_0805_25V6K  [C_0805]  12.56 56.57 0 bottom
CU40  150U_B2_6.3VM_R35M  [C_B2]  12.2 54.26 90 bottom
CU42  47U_0603_6.3V6M  [C_0603]  29.41 48.95 180 top
CU44  47U_0603_6.3V6M  [C_0603]  30.01 49.27 90 bottom
CU45  0.1U_0402_10V7K  [C_0402]  321.71 21.38 0 top
CU46  0.1U_0402_10V7K  [C_0402]  315.3 25.29 90 top
CU47  0.1U_0402_10V7K  [C_0402]  21.46 46.79 0 bottom
CU48  10U_0402_6.3V6M  [C_0402]  316.2 25.3 90 top
CU49  0.22U_0402_10V6K  [C_0402]  16.96 48.45 270 top
CU50  0.22U_0402_10V6K  [C_0402]  17.85 48.45 270 top
CU51  15P_0402_50V  [C_0402]  11.03 54.77 270 top
CU52  15P_0402_50V  [C_0402]  12.35 53.78 270 top
CU53  0.1U_0603_50V7K  [C_0603]  24.06 52.75 225 top
CU54  10U_0603_6.3V6M  [C_0603]  24.89 51.86 225 top
CU55  0.1U_0603_50V7K  [C_0603]  23.06 56.12 90 top
CU56  22U_0402_6.3V6M  [C_0402]  21.14 57.59 0 top
CU65  0.1U_0402_16V7K  [C_0402]  22.87 52.11 0 bottom
CU66  10U_0603_6.3V6M  [C_0603]  16.65 56.32 270 bottom
CU68  1U_0805_25V6K  [C_0805]  19.25 50 90 bottom
CU70  1000P_0402_50V8-J  [C_0402]  15.93 53.14 0 bottom
CU72  1000P_0402_50V8-J  [C_0402]  20.58 50.4 90 bottom
CU76  0.1U_0402_16V7K  [C_0402]  31.21 49.33 180 top
CU77  0.1U_0402_10V7K  [C_0402]  34.31 52.89 180 top
CU78  1U_0402_6.3V6K  [C_0402]  35.89 50.61 270 top
CU79  0.22U_0402_10V6K  [C_0402]  13.97 64.76 0 top
CU80  0.22U_0402_10V6K  [C_0402]  13.97 63.87 0 top
CU81  0.22U_0402_10V6K  [C_0402]  13.59 58.03 0 top
CU82  0.22U_0402_10V6K  [C_0402]  13.59 58.92 0 top
CU83  0.22U_0402_10V6K  [C_0402]  19.63 48.45 270 top
CU84  0.22U_0402_10V6K  [C_0402]  18.74 48.45 270 top
CU85  0.1U_0603_50V7K  [C_0603]  21.03 48.5 0 top
CU86  0.01U_0402_16V7K  [C_0402]  22.37 49.97 180 bottom
CU87  1000P_0402_50V8-J  [C_0402]  17.87 49.8 90 bottom
CU88  1U_0402_6.3V  [C_0402]  14.92 51.43 0 bottom
CU89  1000P_0402_50V8-J  [C_0402]  21.46 52.19 180 bottom
CU90  22U_0402_6.3V6M  [C_0402]  23.32 53.53 225 top
CU91  0.1U_0402_16V7K  [C_0402]  36.78 50.61 270 top
CU92  0.1U_0402_16V7K  [C_0402]  32.52 52.87 90 top
CU93  4.7U_0402_6.3V6M  [C_0402]  16.98 49.99 90 bottom
CV1  0.1U_0201_6.3V6K  [C_0201]  147.07 169.07 270 top
CV2  0.1U_0201_6.3V6K  [C_0201]  147.71 169.07 270 top
CV3  0.1U_0201_6.3V6K  [C_0201]  148.41 169.38 270 top
CV4  0.1U_0201_6.3V6K  [C_0201]  149.04 169.38 270 top
CV5  10U_0603_6.3V6M  [C_0603]  162.25 167.15 90 bottom
CV6  0.1U_0201_6.3V6K  [C_0201]  150.24 169.38 270 top
CV7  0.1U_0201_6.3V6K  [C_0201]  150.47 168.04 270 top
CV8  0.1U_0201_6.3V6K  [C_0201]  149.6 169.38 270 top
CV9  47U_0603_6.3V6M  [C_0603]  163.97 169.98 0 bottom
CV10  10U_0603_6.3V6M  [C_0603]  162.89 171 180 bottom
CV11  0.1U_0201_6.3V6K  [C_0201]  151.1 168.04 270 top
CV12  0.1U_0201_6.3V6K  [C_0201]  151.34 169.38 270 top
CV13  0.1U_0201_6.3V6K  [C_0201]  151.98 169.38 270 top
CV14  0.1U_0603_25V7K  [C_0603]  173.1 184.2 0 top
CV15  1000P_0402_50V7K  [C_0402]  152.79 170.12 270 bottom
CV17  0.1U_0402_10V7K  [C_0402]  164.47 171.02 0 bottom
CV18  10U_0603_6.3V6M  [C_0603]  162.89 169.66 180 bottom
CV19  0.1U_0402_10V7K  [C_0402]  166.98 173.7 180 bottom
CV20  0.1U_0402_16V7K  [C_0402]  223.11 161.84 90 bottom
CV21  4.7U_0805_10V4Z  [C_0805]  166.72 171.69 270 bottom
CV23  0.1U_0201_6.3V6K  [C_0201]  243.66 161.69 90 top
CV24  0.1U_0201_6.3V6K  [C_0201]  226.42 162.23 270 bottom
CV25  0.1U_0201_6.3V6K  [C_0201]  225.85 162.23 270 bottom
CV26  0.1U_0201_6.3V6K  [C_0201]  230.28 168.48 90 bottom
CV27  0.1U_0201_6.3V6K  [C_0201]  229.33 168.48 90 bottom
CV28  0.1U_0201_6.3V6K  [C_0201]  241.48 169.31 90 top
CV29  0.1U_0201_6.3V6K  [C_0201]  234.7 169.37 90 bottom
CV30  0.1U_0201_6.3V6K  [C_0201]  242.37 169.31 90 top
CV31  0.1U_0201_6.3V6K  [C_0201]  235.45 169.37 90 bottom
CV32  0.1U_0201_6.3V6K  [C_0201]  241.65 168.48 90 bottom
CV33  0.1U_0201_6.3V6K  [C_0201]  240.76 168.48 90 bottom
CV34  10U_0402_6.3V6M  [C_0402]  238.73 168.84 180 bottom
CV35  0.1U_0201_6.3V6K  [C_0201]  238.68 169.6 180 bottom
CV36  0.1U_0402_10V7K  [C_0402]  164.55 165.5 0 top
CV37  10P_0402_50V8J  [C_0402]  166.89 166.6 0 bottom
CV372  10U_0603_6.3V6M  [C_0603]  162.38 165.73 180 bottom
CV373  10P_0402_50V8J  [C_0402]  164.46 171.92 0 bottom
CV374  10P_0402_50V8J  [C_0402]  164.35 164.58 0 top
CV375  10P_0402_50V8J  [C_0402]  170.16 184.25 180 top
CV1056  0.1U_0402_16V7K  [C_0402]  211.41 157.52 0 bottom
CV1057  0.1U_0201_6.3V6K  [C_0201]  218.3 166.02 270 bottom
CV1058  0.1U_0201_6.3V6K  [C_0201]  217.74 166.03 270 bottom
CV1059  0.1U_0201_6.3V6K  [C_0201]  212.91 166.07 270 bottom
CV1060  0.1U_0201_6.3V6K  [C_0201]  213.48 166.07 270 bottom
CV1061  0.1U_0201_6.3V6K  [C_0201]  215.34 166.04 270 bottom
CV1062  0.1U_0201_6.3V6K  [C_0201]  215.9 166.04 270 bottom
CV1063  0.1U_0201_6.3V6K  [C_0201]  210.52 166.08 270 bottom
CV1064  0.1U_0201_6.3V6K  [C_0201]  211.1 166.09 270 bottom
CV1068  10U_0603_6.3V6M~D  [C_0603]  222.26 171.12 0 bottom
CV1069  0.1U_0201_6.3V6K  [C_0201]  222.6 172.01 0 bottom
CX1  0.1U_0402_16V7K  [C_0402]  232.21 169.4 270 bottom
CX2  0.1U_0402_16V7K  [C_0402]  209.28 163.21 180 bottom
DA1  -  [BAT54C-7-F_SOT23-3]  38.35 27.23 270 top
DA2  BAT54AW_SOT323-3~D  [BAT54AW_SOT323-3]  36.86 24.37 90 bottom
DA3  BAT54AW_SOT323-3~D  [BAT54AW_SOT323-3]  35.14 43.2 180 top
DA4  AZ5125-02S.R7G_SOT23-3  [AZ5125-02SPR7G_SOT23-3]  22.45 19.99 270 bottom
DA5  AZ5123-02S SOT23  [AZ5125-02SPR7G_SOT23-3]  22.45 19.99 90 top
DA6  AZ5125-02S.R7G_SOT23-3  [AZ5125-02SPR7G_SOT23-3]  21.03 34.88 0 bottom
DA7  AZ5125-02S.R7G_SOT23-3  [AZ5125-02SPR7G_SOT23-3-NPM]  48.77 13.34 90 top
DA8  AZ5125-02S.R7G_SOT23-3  [AZ5125-02SPR7G_SOT23-3-NPM]  48.77 9.34 90 top
DE1  SDMK0340L-7-F_SOD323-2~D  [SDMK0340L-7-F_SOD323-2]  313.26 23.87 0 top
DE2  -  [RB751V-40_SOD323-2]  225.34 38.97 270 bottom
DE3  -  [RB751V-40_SOD323-2]  223.64 38.97 270 bottom
DE4  -  [RB751V-40_SOD323-2]  227.06 38.97 270 bottom
DF1  -  [SDMK0340L-7-F_SOD323-2]  102.93 61.58 270 top
DF2  -  [SDMK0340L-7-F_SOD323-2]  293.45 73.88 180 top
DG2  RB751S40T1G_SOD523-2  [RB520SM-30T2R_EMD2-2]  214.75 112.47 0 bottom
DG3  RB751S40T1G_SOD523-2  [RB520SM-30T2R_EMD2-2]  281.3 173.77 270 top
DG4  RB751S40T1G_SOD523-2  [RB520SM-30T2R_EMD2-2]  213.19 161.08 0 top
DG6  RB751S40T1G_SOD523-2  [RB520SM-30T2R_EMD2-2]  277.59 166.88 270 top
DG7  RB751S40T1G_SOD523-2  [RB520SM-30T2R_EMD2-2]  281.3 169.33 90 top
DG8  RB751S40T1G_SOD523-2  [RB520SM-30T2R_EMD2-2]  186.76 35.87 90 bottom
DG9  RB751S40T1G_SOD523-2  [RB520SM-30T2R_EMD2-2]  188.22 38.67 180 bottom
DH1  -  [RB751V-40_SOD323-2]  201.31 10.02 0 bottom
DK1  -  [TVNST52302AB0_SOT523-3]  144.79 3.6 180 top
DK2  -  [TVNST52302AB0_SOT523-3]  137.09 3.34 180 top
DK3  -  [TVNST52302AB0_SOT523-3]  141.7 4.96 270 top
DS1  SDM10U45-7_SOD523-2~D  [RB520SM-30T2R_EMD2-2]  188.13 66.54 270 top
DT1  SDM10U45-7_SOD523-2~D  [RB520SM-30T2R_EMD2-2]  190.78 177.09 90 top
DT2  AZ5B75-01B  [ESD108-B1-CSP0201_WLL-2-1-2]  190.12 177.64 180 bottom
DT3  AZ5B75-01B  [ESD108-B1-CSP0201_WLL-2-1-2]  190.78 177.64 0 bottom
DT4  AZ5B75-01B  [ESD108-B1-CSP0201_WLL-2-1-2]  187.21 176.33 180 bottom
DT5  AZ5B75-01B  [ESD108-B1-CSP0201_WLL-2-1-2]  187.91 176.33 0 bottom
DT6  AZ5B75-01B  [ESD108-B1-CSP0201_WLL-2-1-2]  196.27 175.92 0 top
DT7  AZ5B75-01B  [ESD108-B1-CSP0201_WLL-2-1-2]  195.61 175.92 180 top
DT8  AZ5B75-01B  [ESD108-B1-CSP0201_WLL-2-1-2]  196.31 175.92 0 bottom
DT9  AZ5B75-01B  [ESD108-B1-CSP0201_WLL-2-1-2]  195.61 175.92 180 bottom
DT10  -  [TVWDF1004AD0_DFN9]  191.81 176.17 0 bottom
DT11  AZ5B75-01B  [ESD108-B1-CSP0201_WLL-2-1-2]  191.27 175.57 0 top
DT12  AZ5B75-01B  [ESD108-B1-CSP0201_WLL-2-1-2]  196.9 177.67 90 top
DT13  AZ5B75-01B  [ESD108-B1-CSP0201_WLL-2-1-2]  194.8 177.66 90 top
DT14  AZ5B75-01B  [ESD108-B1-CSP0201_WLL-2-1-2]  188.56 177.92 180 top
DT15  AZ4024-02S_SOT23-3~D  [PESD24VS2UT_SOT23-3]  207.53 169.13 0 bottom
DU1  -  [L30ESDL5V0C3-2_SOT23-3]  20.37 38.15 90 bottom
DU2  -  [TVWDF1004AD0_DFN9]  20.23 39.29 90 top
DU6  -  [SDMK0340L-7-F_SOD323-2]  32.46 48.05 270 top
DU8  -  [SDMK0340L-7-F_SOD323-2]  34.16 48.09 270 top
DU11  -  [L30ESDL5V0C3-2_SOT23-3]  11.86 61.52 90 bottom
DU20  L05ESDL5V0NA-4_SLP2510P8-10-9  [TVWDF1004AD0_DFN9]  13.34 65.58 90 bottom
DU22  AZ5B75-01B  [ESD108-B1-CSP0201_WLL-2-1-2]  11.27 65.67 270 top
DU23  AZ5B75-01B  [ESD108-B1-CSP0201_WLL-2-1-2]  11.27 66.34 90 top
DU24  AZ5B75-01B  [ESD108-B1-CSP0201_WLL-2-1-2]  10.49 64.6 90 top
DU25  AZ5B75-01B  [ESD108-B1-CSP0201_WLL-2-1-2]  10.49 63.91 270 top
DU26  AZ5B75-01B  [ESD108-B1-CSP0201_WLL-2-1-2]  10.17 58.78 90 top
DU27  AZ5B75-01B  [ESD108-B1-CSP0201_WLL-2-1-2]  10.17 58.12 270 top
DU28  AZ5B75-01B  [ESD108-B1-CSP0201_WLL-2-1-2]  10.87 61.07 90 top
DU29  AZ5B75-01B  [ESD108-B1-CSP0201_WLL-2-1-2]  10.87 60.4 270 top
DV1  -  [RB751V-40_SOD323-2]  168.74 161.19 0 top
DV2  -  [PESD5V0U2BT_SOT23-3]  162.7 166.34 0 top
DV4  -  [AZC199-02SPR7G_SOT23-3]  167.05 166.37 0 top
DV12  SDM10U45-7_SOD523-2  [RB520SM-30T2R_EMD2-2]  222.89 168.23 90 bottom
DV13  SDM10U45-7_SOD523-2  [RB520SM-30T2R_EMD2-2]  221.62 168.23 90 bottom
FD1  FIDUCIAL  [FIDUCIAL_C40M80]  280.68 154.87 90 top
FD2  FIDUCIAL  [FIDUCIAL_C40M80]  63.56 7.85 0 top
FD3  FIDUCIAL  [FIDUCIAL_C40M80]  4.52 3.67 180 bottom
FD4  FIDUCIAL  [FIDUCIAL_C40M80]  282.08 170.77 180 bottom
FD5  FIDUCIAL  [FIDUCIAL_C40M80]  334.53 27.33 0 top
FD6  FIDUCIAL  [FIDUCIAL_C40M80]  321.1 7.86 180 bottom
FV2  1.1A_6V_SPR-P110  [F_SPR-P110]  243.93 165.85 180 top
FV3  1.1A_6V_SPR-P110  [F_SPR-P110]  225.12 171.21 270 bottom
H1  -  [H_3P8]  144.97 157.4 0 top
H2  -  [H_3P8]  122.67 92.7 0 top
H3  -  [H_3P6]  181.67 92.1 0 top
H4  -  [H_3P8]  205.07 50.3 0 top
H5  -  [H_3P8]  276.07 45.3 0 top
H6  -  [H_3P0]  179.67 8.3 0 top
H7  -  [H_3P8]  269.07 152.3 0 top
H8  -  [H_3P0]  5.07 71.6 0 top
H9  -  [H_3P0]  6.57 52.6 0 top
H10  -  [H_3P0]  28.07 55.8 0 top
H11  -  [H_3P6]  22.07 13.3 0 top
H12  -  [H_3P0]  276.17 172.4 0 top
H13  -  [H_3P6X4P2]  199.57 153.8 0 top
H14  -  [H_3P0]  202.22 181.9 0 top
H15  -  [H_3P0]  183.22 181.9 0 top
H16  -  [H_3P0]  22.07 6 0 top
H17  -  [H_3P0]  144.57 173.3 0 top
H18  -  [H_3P0]  102.07 8.3 0 top
H19  -  [H_3P0]  92.87 58.7 0 top
H20  -  [H_3P0]  297.87 78.05 0 top
H21  -  [H_3P0]  262.07 8.3 0 top
H22  -  [H_3P0]  197.87 57.4 0 top
H23  -  [H_4P1X3P6]  267.97 8.3 0 top
J4  -  [JUMP_43X79]  58.75 14.31 90 bottom
J5  -  [JUMP_43X79]  70.66 15.87 180 bottom
J6  -  [JUMP_43X79]  225.39 39.81 0 top
J7  -  [JUMP_43X79]  28.22 5.58 0 bottom
JACK1  YUQIU_PJ741-F07J1BE-C  [YUQIU_PJ741-F07J1BE-C_6P-T]  13.47 6.1 90 bottom
JACK2  YUQIU_PJ741-F07J1BE-C  [YUQIU_PJ741-F07J1BE-C_6P-T]  13.47 18.8 90 bottom
JCDRA  TE_2260531-1  [TE_2260531-1_46P]  151.87 179.51 0 bottom
JDIMM1  DEREN_40-42271-26001RHF  [DEREN_40-42271-26001RHF_260P-T]  111.69 61.8 0 bottom
JDIMM2  DEREN_40-42261-26001RHF  [DEREN_40-42261-26001RHF_260P-T]  111.69 49 180 bottom
JDP  ACON_MAR2F-20K1800  [ACON_MAR2F-20K1800_20P]  232.37 175.49 180 bottom
JEDP  ACES_50473-0400M-P01  [ACES_50473-0400M-P01_40P]  151.62 182.07 0 top
JELC1  AMPHE_G846A06211EU  [AMPHE_G846A06201EU_6P-T-NPM]  166.6 28.34 0 bottom
JELC2  CVILU_CH51102M100-0P  [CVILU_CH51102M100-0P_10P-T]  155.9 32.38 270 bottom
JFAN1  ACES_50278-00401-001  [ACES_50278-00401-001_4P]  106.87 65.1 180 top
JFAN2  ACES_50278-00401-001  [ACES_50278-00401-001_4P]  290.87 79.05 180 top
JHDD  STARC_111H30-000000-G4-R  [STARC_111H30-000000-G4-R_30P]  113.42 11.75 0 bottom
JHDMI  ACON_HMRA3-AK1L0C  [ACON_HMRA3-AK1L0C_19P]  212.12 176.1 0 bottom
JIO  ACES_50473-0300M-P01  [ACES_50473-0300M-P01_30P]  325.55 11.66 90 top
JKB  ACES_50552-03001-P01  [ACES_50552-03001-P01_30P]  223.47 9.55 180 bottom
JKB2  -  [ACES_50611-0100N-001_10P]  139.38 12.98 0 bottom
JKB3  ACES_87153-06411  [ACES_87153-06411_6P]  64.93 6.73 180 bottom
JKBBL  ACES_50552-02001-P01  [ACES_50552-02001-P01_20P]  169.82 9.55 180 bottom
JLAN  SANTA_130456-512  [SANTA_130456-512_13P]  249.64 173.57 0 bottom
JLOGO  ACES_87212-1600L  [ACES_87212-1600L_16P]  221.92 167.99 0 top
JP1  PAD-OPEN 43x39  [JUMP_43X39]  198.62 41.96 0 top
JP3  -  [JUMP_43X118]  130.61 11.04 180 top
JPCMC  INTEL_CMC_PRIMARY  [INTEL_CMC_PRIMARY_36P-T]  122.87 159.13 270 top
JPK  ACES_50552-02001-P01  [ACES_50552-02001-P01_20P]  148.58 4.18 180 bottom
JPWR  ACES_87153-06411  [ACES_87153-06411_6P]  210.32 167.92 0 top
JRTC1  ACES_50271-00201-001  [ACES_50271-00201-001_2P]  292.69 38.9 180 bottom
JSPK  ACES_50278-00601-001  [ACES_50278-00601-001_6P-T]  52.18 15.96 180 bottom
JSSD1  LCN_DAN05-67406-0103  [LCN_DAN05-67406-0103_75P-T]  325.85 49.91 270 bottom
JSSD2  LCN_DAN05-67406-0103  [LCN_DAN05-67406-0103_75P-T]  271.85 26.06 270 bottom
JSSD3  LCN_DAN05-67406-0103  [LCN_DAN05-67406-0103_75P-T]  254.02 14.72 180 bottom
JTOBII  ACES_50450-0067N-P01  [ACES_50450-0067N-P01_6P]  154.56 167.55 0 top
JTP  ACES_51522-01601-P01  [ACES_51522-01601-P01_16P]  196.82 12.9 180 bottom
JTRONL  ACES_50450-0127N-001  [ACES_50450-0127N-001_12P]  43.47 51.05 180 bottom
JTRONR  ACES_50450-0127N-001  [ACES_50450-0127N-001_12P]  274.77 32.4 0 bottom
JUSB1  SDAN_608015-010232  [SDAN_608015-010232_10P]  16.55 43.2 90 bottom
JUSBC1  -  [JAE_DX07S024JJ5_24P-T]  190.1 179.8 0 bottom
JUSBC2  -  [JAE_DX07S024JJ5_24P-T]  7.55 64.73 270 top
JWDB  ACES_88266-04001  [ACES_50207-00471-P01_4P-T]  205.49 12.22 0 top
JWLAN  LCN_DAN05-67306-0102  [LCN_DAN05-67306-0102_67P]  300.32 35.37 0 bottom
LA3  BLM15AG121SN1D_L0402_2P  [MURAT_BLM15AG121SN1D_L0402_2P]  33.82 23.61 0 bottom
LA4  BLM15AG121SN1D_L0402_2P  [MURAT_BLM15AG121SN1D_L0402_2P]  30.83 23.56 0 bottom
LA5  BLM15AG121SN1D_L0402_2P  [MURAT_BLM15AG121SN1D_L0402_2P]  40.8 32.7 90 top
LA6  BLM15BB221SN1D_2P  [MURAT_BLM15BB221SN1D_2P]  35.8 38.85 180 bottom
LA7  BLM15PX330SN1D 0402  [MURAT_BLM15BD601SN1D_2P]  26.93 20.56 180 bottom
LA8  BLM15PX330SN1D 0402  [MURAT_BLM15BD601SN1D_2P]  27.76 22.72 0 top
LA9  FBMA-L11-160808-800LMT_2P  [KC_FBMA-L10-160808-800LMT_2P]  24.52 20.36 270 bottom
LA10  FBMA-L11-160808-800LMT_2P  [KC_FBMA-L10-160808-800LMT_2P]  17.42 25.04 270 bottom
LA11  BLM15PX330SN1D 0402  [MURAT_BLM15BD601SN1D_2P]  21.93 24.05 0 top
LA12  BLM15PX330SN1D 0402  [MURAT_BLM15BD601SN1D_2P]  21.93 25.7 0 top
LA50  BLM15PX121SN1D_2P  [MURAT_BLM15PX121SN1D_2P]  37.21 5.9 270 top
LA51  BLM15PX121SN1D_2P  [MURAT_BLM15PX121SN1D_2P]  36.71 5.01 180 bottom
LA52  BLM15PX121SN1D_2P  [MURAT_BLM15PX121SN1D_2P]  32.51 4.88 270 top
LA53  BLM15PX121SN1D_2P  [MURAT_BLM15PX121SN1D_2P]  30.99 6.21 180 top
LE1  FBMA-L11-160808-800LMT_0603  [KC_FBMA-L11-160808-800LMT_2P]  289.23 27.47 180 top
LE2  FBMA-L11-160808-800LMT_0603  [KC_FBMA-L11-160808-800LMT_2P]  286.08 11.67 0 top
LE3  MCM1012B900F06BP_4P  [INPAQ_MCM1012B900F06BP_4P-NPM]  157.37 166.1 90 bottom
LE4  BLM15AG121SN1D_L0402_2P  [MURAT_BLM15AG121SN1D_L0402_2P]  313.23 28.37 0 top
LG1  PBY160808T-301Y-N  [CHILI_PBY160808T-300Y-N_2P]  219.67 110.8 180 top
LG2  PBY160808T-300Y-N_2P  [CHILI_PBY160808T-300Y-N_2P]  203.53 108.05 90 top
LG3  PBY160808T-300Y-N_2P  [CHILI_PBY160808T-300Y-N_2P]  225.62 119.39 270 top
LG4  PBY160808T-301Y-N  [CHILI_PBY160808T-300Y-N_2P]  222.89 119.39 270 top
LG5  PBY160808T-300Y-N_2P  [CHILI_PBY160808T-300Y-N_2P]  224.53 122.42 0 top
LG6  PBY160808T-300Y-N_2P  [CHILI_PBY160808T-300Y-N_2P]  202.07 108.05 90 top
LL1  BLM15AG121SN1D_L0402_2P  [MURAT_BLM15AG121SN1D_L0402_2P]  265.88 158.19 90 top
LM1  MCM1012B900F06BP_4P  [INPAQ_MCM1012B900F06BP_4P]  168.47 175.07 90 bottom
LT1  0.6UH_MND-04ABIR60M-XGL_20%  [MAG_MND-04ABIR60M-XGL_2P]  172.92 170.78 90 bottom
LT2  MCM1012B900F06BP_4P  [INPAQ_MCM1012B900F06BP_4P]  192.27 172.69 90 bottom
LT3  MCM1012B900F06BP_4P  [INPAQ_MCM1012B900F06BP_4P]  193.85 172.69 90 bottom
LT4  1UH_LQM18PN1R0MFHD_20%  [MURAT_LQM18PN1R0MFHD_2P]  175.9 170.65 90 bottom
LU3  MCM1012B900F06BP_4P  [INPAQ_MCM1012B900F06BP_4P]  24.4 42.4 270 bottom
LU4  HCM1012GD670A05P  [INPAQ_MCM1012B900F06BP_4P]  22.9 40.8 180 top
LU5  HCM1012GD670A05P  [INPAQ_MCM1012B900F06BP_4P]  22.9 39.28 180 top
LU7  HCM1012GD670A05P  [INPAQ_MCM1012B900F06BP_4P]  13.85 65.83 180 top
LU8  HCM1012GD670A05P  [INPAQ_MCM1012B900F06BP_4P]  12.7 64 180 top
LU9  MCM1012B900F06BP_4P  [INPAQ_MCM1012B900F06BP_4P]  16.16 59.82 90 bottom
LU10  HCM1012GD670A05P  [INPAQ_MCM1012B900F06BP_4P]  13.08 60.51 180 top
LU11  HCM1012GD670A05P  [INPAQ_MCM1012B900F06BP_4P]  12.36 58.22 180 top
LU13  3.3UH_UHP252010BF-3R3M_20%  [TAI-T_UHP252010BF-3R3M_2P]  22.89 53.95 180 bottom
LU14  PBY160808T-300Y-N_2P  [CHILI_PBY160808T-300Y-N_2P]  29.86 50.92 0 top
LU17  PBY160808T-300Y-N_2P  [CHILI_PBY160808T-300Y-N_2P]  15.19 50.5 270 bottom
LU18  PBY160808T-300Y-N_2P  [CHILI_PBY160808T-300Y-N_2P]  21.13 56.99 270 bottom
LV2  MCM1012B900F06BP_4P  [INPAQ_MCM1012B900F06BP_4P]  167.02 163.2 90 top
LV3  HCM1012GH900BP_4P  [INPAQ_HCM1012GH900BP_4P]  218.22 167.45 90 bottom
LV4  HCM1012GH900BP_4P  [INPAQ_HCM1012GH900BP_4P]  213.42 167.45 90 bottom
LV5  HCM1012GH900BP_4P  [INPAQ_HCM1012GH900BP_4P]  215.83 167.45 90 bottom
LV6  HCM1012GH900BP_4P  [INPAQ_HCM1012GH900BP_4P]  211.03 167.45 90 bottom
LX1  PBY100505T-601Y-N_2P  [CHILI_PBY100505T-300Y-N_2P]  214.54 162.93 270 top
LX2  PBY100505T-601Y-N_2P  [CHILI_PBY100505T-300Y-N_2P]  213.39 162.93 270 top
LX3  PBY100505T-601Y-N_2P  [CHILI_PBY100505T-300Y-N_2P]  219.17 162.89 270 top
LX4  PBY100505T-601Y-N_2P  [CHILI_PBY100505T-300Y-N_2P]  218.02 162.89 270 top
LX5  PBY100505T-601Y-N_2P  [CHILI_PBY100505T-300Y-N_2P]  216.85 162.96 270 top
LX6  PBY100505T-601Y-N_2P  [CHILI_PBY100505T-300Y-N_2P]  215.69 162.96 270 top
LX7  PBY100505T-601Y-N_2P  [CHILI_PBY100505T-300Y-N_2P]  212.24 162.93 270 top
LX8  PBY100505T-601Y-N_2P  [CHILI_PBY100505T-300Y-N_2P]  211.1 162.93 270 top
NOREF  -  []  276.07 45.3 0 top
NOREF#2  -  []  144.57 173.3 0 top
NOREF#3  -  []  124.84 34.24 0 top
NOREF#4  -  []  297.87 78.05 0 top
NOREF#5  -  []  250.86 42.55 0 top
NOREF#6  -  []  205.07 50.3 0 top
NOREF#7  -  []  120.07 74.65 0 top
NOREF#8  -  []  153.78 19.14 0 top
NOREF#9  -  []  276.17 172.4 0 top
NOREF#10  -  []  199.57 153.8 0 top
NOREF#11  -  []  92.87 58.7 0 top
NOREF#12  -  []  150.75 -26.59 0 top
NOREF#13  -  []  140.14 27.05 90 top
NOREF#14  -  []  109.74 239.96 0 top
NOREF#15  -  []  28.07 55.8 0 top
NOREF#16  -  []  181.67 92.1 0 top
NOREF#17  -  []  269.07 152.3 0 top
NOREF#18  -  []  144.57 173.3 0 top
NOREF#19  -  []  144.97 157.4 0 top
NOREF#20  -  []  153.83 69.61 0 top
NOREF#21  -  []  122.67 92.7 0 top
NOREF#22  -  []  197.87 57.4 0 top
NOREF#23  -  []  179.67 8.3 0 top
NOREF#24  -  []  88.35 12 0 top
NOREF#25  -  []  102.07 8.3 0 top
NOREF#26  -  []  258.25 76.6 180 bottom
NOREF#27  -  []  166.21 85.8 180 bottom
PBATT1  ACES_50290-01201-P01  [ACES_50290-01201-P01_12P-T]  91.82 15.75 180 bottom
PC1  1000P_0402_50V7K  [C_0402]  84.1 39.55 90 bottom
PC2  1000P_0402_50V7K  [C_0402]  85.2 39.52 90 bottom
PC3  1000P_0402_50V7K  [C_0402]  75.57 34.5 270 bottom
PC4  1000P_0402_50V7K  [C_0402]  74.68 34.5 270 bottom
PC6  0.022U_0402_25V7K  [C_0402]  88.4 28.57 90 bottom
PC7  0.01UF_0402_25V7K  [C_0402]  87.51 28.57 90 bottom
PC8  1000P_0402_50V7K  [C_0402]  83.08 22.01 180 top
PC9  100P_0402_50V8J  [C_0402]  83.07 21.07 180 top
PC10  0.22U_0603_25V7K  [C_0603]  73.73 11.17 180 top
PC11  0.1U_0402_25V6  [C_0402]  67 15.41 90 top
PC12  .1U_0402_16V7K  [C_0402]  68.88 9.99 270 top
PC13  .1U_0402_16V7K  [C_0402]  293.21 8.12 270 top
PC14  1U_0603_25V6K  [C_0603]  82.41 9.62 180 top
PC15  0.1U_0402_25V6  [C_0402]  121.07 81.13 270 top
PC100  0.1U_0402_25V6  [C_0402]  51.38 40.52 270 top
PC101  4.7U_0603_6.3V6K  [C_0603]  53.95 50.36 90 bottom
PC102  22U_0805_25V6M  [C_0805]  52.4 35.61 180 top
PC103  2200P_0402_50V7K  [C_0402]  52.28 38.73 180 top
PC104  22U_0805_25V6M  [C_0805]  48.27 40.53 270 top
PC105  0.1U_0402_25V6  [C_0402]  57.53 47.55 0 bottom
PC106  0.1U_0402_25V6  [C_0402]  49.2 47.41 0 bottom
PC108  220U_D2_6.3VY_R15M  [C_D2]  32.95 41.37 90 bottom
PC109  680P_0603_50V8J  [C_0603]  43.76 32.6 0 top
PC110  680P_0603_50V8J  [C_0603]  44.08 33.8 0 top
PC111  4.7U_0603_6.3V6K  [C_0603]  53.73 44.12 0 bottom
PC112  4.7U_0603_6.3V6K  [C_0603]  61.65 49.08 0 top
PC113  22U_0805_25V6M  [C_0805]  50.05 40.53 270 top
PC114  22U_0805_25V6M  [C_0805]  52.39 37.38 180 top
PC115  220U_D2_6.3VY_R15M  [C_D2]  37.65 41.37 90 bottom
PC116  220U_D2_6.3VY_R15M  [C_D2]  42.3 20.56 180 bottom
PC117  220U_D2_6.3VY_R15M  [C_D2]  41.86 25.01 90 bottom
PC118  1U_0402_25V6K  [C_0402]  53.97 33.71 270 top
PC119  1000P_0402_50V7K  [C_0402]  54.93 33.71 270 top
PC200  0.1U_0402_25V6  [C_0402]  92.72 35.16 0 top
PC201  2200P_0402_50V7K  [C_0402]  92.72 36.05 0 top
PC202  10U_0805_25V6K~D  [C_0805]  92.73 34.17 270 top
PC203  10U_0805_25V6K~D  [C_0805]  91.03 34.28 270 top
PC204  0.1U_0603_25V7K  [C_0603]  88.21 43.81 0 bottom
PC205  10U_0805_6.3V6K  [C_0805]  91.41 49.33 180 bottom
PC206  10U_0805_6.3V6K  [C_0805]  91.41 51.17 180 bottom
PC207  1U_0603_10V6K  [C_0603]  93.61 41.2 90 bottom
PC208  1U_0402_25V6K  [C_0402]  88.64 36.95 90 top
PC209  220U 2.5V Y D2 ESR9M H1.9 SX  [C_D2]  96.27 30.85 270 bottom
PC210  0.033U_0402_16V7K  [C_0402]  92.91 48.94 90 bottom
PC211  680P_0402_50V7K  [C_0402]  97.27 36.08 180 top
PC212  1U_0603_10V6K  [C_0603]  94.94 42.6 270 bottom
PC213  0.1U_0402_10V7K  [C_0402]  95.88 46.35 0 bottom
